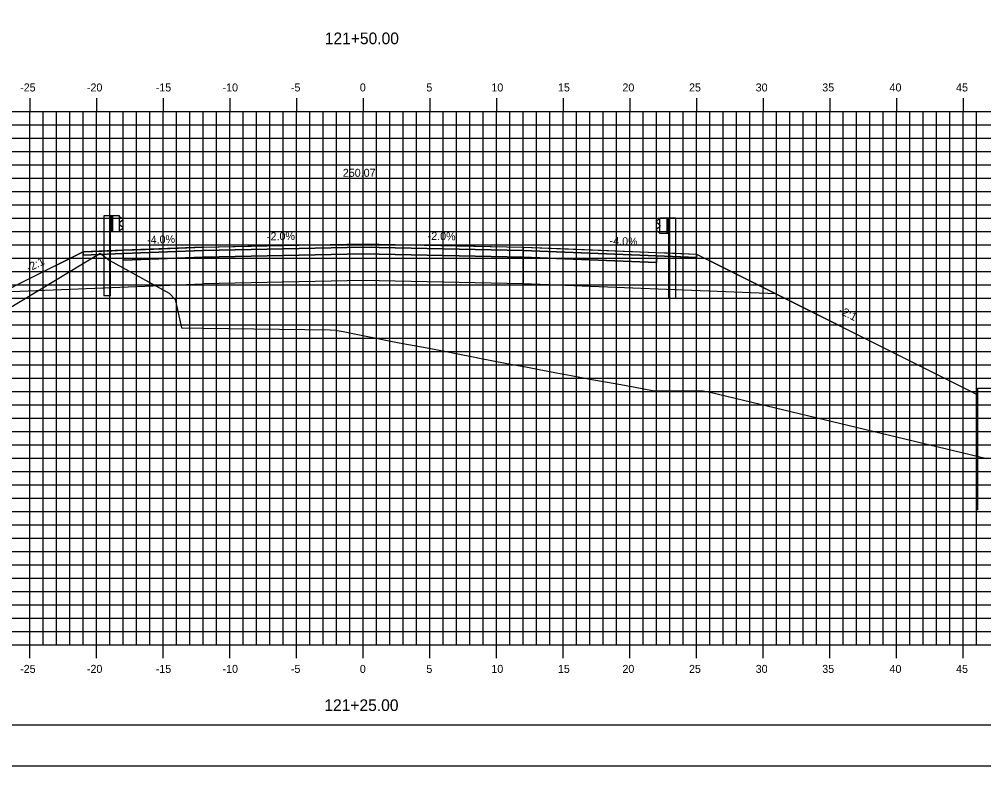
# Model space of a CAD drawing. Extents: x -22 to 1480, y -1511 to 8.
# Drawn here: x 1049.4 to 1121.7, y -1511.4 to -1455.4 of the extents above; entities that cross this region are included whole.
import ezdxf

# ---------------------------------------------------------------- set-up
doc = ezdxf.new("R2010")
doc.units = 0
for name, color, linetype in [('ANNOTATION', 7, 'Continuous'), ('BORDER', 7, 'Continuous'), ('D_Bridge_Wingwall', 7, 'Continuous'), ('D_Guardrail_Beam_Lt', 7, 'Continuous'), ('D_Guardrail_Beam_Rt', 7, 'Continuous'), ('D_Roadway_Centerline', 7, 'Continuous'), ('D_Roadway_Centerline_Text', 7, 'Continuous'), ('D_Roadway_Edge_Shoulder', 7, 'Continuous'), ('D_Roadway_Edge_TW', 7, 'Continuous'), ('D_Roadway_Pavement', 7, 'Continuous'), ('D_Roadway_SlopeLines', 7, 'Continuous'), ('D_Roadway_SubGrade', 7, 'Continuous'), ('H_V ANNOTATION', 7, 'Continuous'), ('MAJOR', 7, 'Continuous'), ('MINOR', 7, 'Continuous'), ('PLOT BOUNDARY', 7, 'Continuous'), ('S_Roadway_Centerline', 7, 'Continuous')]:
    doc.layers.add(name, color=color, linetype=linetype)

msp = doc.modelspace()

# ---------------------------------------------------------------- linework, layer by layer
at = {"layer": 'BORDER'}
msp.add_line((1000.183, -1508.331), (1160.183, -1508.331), dxfattribs=at)
at = {"layer": 'D_Bridge_Wingwall'}
msp.add_lwpolyline([(1121.282, -1492.231), (1121.282, -1483.073), (1123.425, -1483.073), (1123.425, -1483.073), (1123.425, -1492.435)], dxfattribs=at)
at = {"layer": 'D_Guardrail_Beam_Lt'}
for p, q in [((1055.753, -1470.16), (1055.753, -1476.16)), ((1056.224, -1470.16), (1055.753, -1470.16)), ((1056.912, -1470.16), (1056.224, -1470.16)), ((1056.224, -1470.16), (1056.224, -1471.327)), ((1056.287, -1470.16), (1056.287, -1471.327)), ((1056.391, -1470.16), (1056.391, -1471.327)), ((1056.912, -1471.327), (1056.912, -1470.16)), ((1056.912, -1470.243), (1056.986, -1470.258)), ((1057.002, -1470.265), (1057.145, -1470.364)), ((1056.916, -1470.708), (1056.916, -1470.778)), ((1057.145, -1470.508), (1056.95, -1470.644)), ((1056.95, -1470.843), (1057.145, -1470.979)), ((1057.145, -1471.122), (1057.002, -1471.222)), ((1056.224, -1471.327), (1056.912, -1471.327)), ((1056.245, -1476.16), (1056.245, -1471.327)), ((1056.986, -1471.229), (1056.912, -1471.243)), ((1056.245, -1476.16), (1055.753, -1476.16))]:
    msp.add_line(p, q, dxfattribs=at)
for centre, major_axis, start_param, end_param in [((1056.978, -1470.298), (0.0417, 0), 0.959931, 1.376053), ((1057.095, -1470.436), (0.0877, 0), 5.323254, 7.243116), ((1056.995, -1470.708), (-0.0789, 0), 5.323254, 6.283185), ((1056.995, -1470.778), (-0.0789, 0), 6.283185, 7.243116), ((1057.095, -1471.05), (0.0877, 0), 5.323254, 7.243116), ((1056.978, -1471.188), (0.0417, 0), 4.907132, 5.323254)]:
    msp.add_ellipse(centre, major_axis=major_axis, ratio=0.995501, start_param=start_param, end_param=end_param, dxfattribs=at)
at = {"layer": 'D_Guardrail_Beam_Rt'}
for p, q in [((1097.363, -1470.425), (1097.22, -1470.524)), ((1097.453, -1470.403), (1097.379, -1470.418)), ((1097.453, -1470.32), (1098.141, -1470.32)), ((1097.453, -1471.487), (1097.453, -1470.32)), ((1097.974, -1470.32), (1097.974, -1471.487)), ((1098.078, -1470.32), (1098.078, -1471.487)), ((1098.141, -1470.32), (1098.612, -1470.32)), ((1098.141, -1470.32), (1098.141, -1471.487)), ((1098.612, -1470.32), (1098.612, -1476.32)), ((1097.22, -1470.668), (1097.415, -1470.804)), ((1097.415, -1471.003), (1097.22, -1471.139)), ((1097.449, -1470.868), (1097.449, -1470.938)), ((1097.22, -1471.282), (1097.363, -1471.382)), ((1097.379, -1471.389), (1097.453, -1471.403)), ((1098.141, -1471.487), (1097.453, -1471.487)), ((1098.12, -1476.32), (1098.12, -1471.487)), ((1098.12, -1476.32), (1098.612, -1476.32))]:
    msp.add_line(p, q, dxfattribs=at)
for centre, major_axis, start_param, end_param in [((1097.387, -1470.458), (-0.0417, 0), 4.907132, 5.323254), ((1097.27, -1470.596), (-0.0877, 0), 5.323254, 7.243116), ((1097.27, -1471.21), (-0.0877, 0), 5.323254, 7.243116), ((1097.37, -1470.868), (0.0789, 0), 0, 0.959931), ((1097.37, -1470.938), (0.0789, 0), 5.323254, 6.283185), ((1097.387, -1471.348), (-0.0417, 0), 0.959931, 1.376053)]:
    msp.add_ellipse(centre, major_axis=major_axis, ratio=0.995501, start_param=start_param, end_param=end_param, dxfattribs=at)
at = {"layer": 'D_Roadway_Centerline'}
msp.add_lwpolyline([(1031.762, -1484.073), (1041.448, -1479.231), (1045.248, -1477.33), (1048.204, -1475.852), (1049.878, -1475.015), (1054.183, -1472.863), (1056.343, -1472.777), (1057.183, -1472.743), (1058.863, -1472.676), (1063.183, -1472.503), (1066.543, -1472.436), (1075.183, -1472.263), (1078.543, -1472.33), (1087.183, -1472.503), (1089.983, -1472.615), (1097.183, -1472.903), (1098.023, -1472.937), (1100.183, -1473.023), (1101.856, -1473.86), (1106.161, -1476.012), (1115.503, -1480.683), (1121.282, -1483.573)], dxfattribs=at)
at = {"layer": 'D_Roadway_Edge_Shoulder'}
for points in [[(1063.183, -1472.503), (1057.183, -1472.743), (1057.183, -1472.743), (1054.183, -1472.863), (1054.183, -1473.113), (1057.183, -1472.993), (1057.183, -1472.993), (1063.183, -1472.753)], [(1087.183, -1472.503), (1097.183, -1472.903), (1097.183, -1472.903), (1100.183, -1473.023), (1100.183, -1473.273), (1097.183, -1473.153), (1097.183, -1473.153), (1087.183, -1472.753)]]:
    msp.add_lwpolyline(points, close=True, dxfattribs=at)
at = {"layer": 'D_Roadway_Edge_TW'}
msp.add_lwpolyline([(1063.183, -1472.753), (1063.183, -1472.503), (1075.183, -1472.263), (1087.183, -1472.503), (1087.183, -1472.753), (1075.183, -1472.513)], close=True, dxfattribs=at)
at = {"layer": 'D_Roadway_Pavement'}
msp.add_lwpolyline([(1063.183, -1473.253), (1063.183, -1472.753), (1075.183, -1472.513), (1087.183, -1472.753), (1087.183, -1473.253), (1075.183, -1473.013)], close=True, dxfattribs=at)
for points in [[(1063.183, -1472.753), (1057.183, -1472.993), (1057.183, -1472.993), (1057.183, -1473.493), (1063.183, -1473.253), (1063.183, -1472.753)], [(1087.183, -1472.753), (1097.183, -1473.153), (1097.183, -1473.153), (1097.183, -1473.653), (1087.183, -1473.253), (1087.183, -1472.753)]]:
    msp.add_lwpolyline(points, dxfattribs=at)
at = {"layer": 'D_Roadway_SlopeLines'}
for points in [[(1054.183, -1472.863), (1031.762, -1484.073)], [(1100.183, -1473.023), (1121.282, -1483.573)]]:
    msp.add_lwpolyline(points, dxfattribs=at)
at = {"layer": 'D_Roadway_SubGrade'}
for points in [[(1063.183, -1473.253), (1057.183, -1473.493), (1057.183, -1472.993), (1054.183, -1473.113), (1054.183, -1472.863), (1048.204, -1475.852), (1063.183, -1475.253)], [(1063.183, -1475.253), (1063.183, -1473.253), (1075.183, -1473.013), (1087.183, -1473.253), (1087.183, -1475.253), (1075.183, -1475.013)], [(1087.183, -1473.253), (1097.183, -1473.653), (1097.183, -1473.153), (1100.183, -1473.273), (1100.183, -1473.023), (1106.161, -1476.012), (1087.183, -1475.253)]]:
    msp.add_lwpolyline(points, close=True, dxfattribs=at)
at = {"layer": 'MAJOR'}
for p, q in [((1050.183, -1461.329), (1050.183, -1462.331)), ((1055.183, -1461.329), (1055.183, -1462.331)), ((1060.183, -1461.329), (1060.183, -1462.331)), ((1065.183, -1461.329), (1065.183, -1462.331)), ((1070.183, -1461.329), (1070.183, -1462.331)), ((1075.183, -1461.329), (1075.183, -1462.331)), ((1080.183, -1461.329), (1080.183, -1462.331)), ((1085.183, -1461.329), (1085.183, -1462.331)), ((1090.183, -1461.329), (1090.183, -1462.331)), ((1095.183, -1461.329), (1095.183, -1462.331)), ((1100.183, -1461.329), (1100.183, -1462.331)), ((1105.183, -1461.329), (1105.183, -1462.331)), ((1110.183, -1461.329), (1110.183, -1462.331)), ((1115.183, -1461.329), (1115.183, -1462.331)), ((1120.183, -1461.329), (1120.183, -1462.331)), ((1005.183, -1462.331), (1145.183, -1462.331)), ((1005.183, -1462.331), (1145.183, -1462.331)), ((1050.183, -1502.331), (1050.183, -1462.331)), ((1055.183, -1502.331), (1055.183, -1462.331)), ((1060.183, -1502.331), (1060.183, -1462.331)), ((1065.183, -1502.331), (1065.183, -1462.331)), ((1070.183, -1502.331), (1070.183, -1462.331)), ((1075.183, -1502.331), (1075.183, -1462.331)), ((1080.183, -1502.331), (1080.183, -1462.331)), ((1085.183, -1502.331), (1085.183, -1462.331)), ((1090.183, -1502.331), (1090.183, -1462.331)), ((1095.183, -1502.331), (1095.183, -1462.331)), ((1100.183, -1502.331), (1100.183, -1462.331)), ((1105.183, -1502.331), (1105.183, -1462.331)), ((1110.183, -1502.331), (1110.183, -1462.331)), ((1115.183, -1502.331), (1115.183, -1462.331)), ((1120.183, -1502.331), (1120.183, -1462.331)), ((1005.183, -1467.331), (1145.183, -1467.331)), ((1005.183, -1472.331), (1145.183, -1472.331)), ((1005.183, -1477.331), (1145.183, -1477.331)), ((1005.183, -1482.331), (1145.183, -1482.331)), ((1005.183, -1487.331), (1145.183, -1487.331)), ((1005.183, -1492.331), (1145.183, -1492.331)), ((1005.183, -1497.331), (1145.183, -1497.331)), ((1005.183, -1502.331), (1145.183, -1502.331)), ((1005.183, -1502.331), (1145.183, -1502.331)), ((1050.183, -1503.333), (1050.183, -1502.331)), ((1055.183, -1503.333), (1055.183, -1502.331)), ((1060.183, -1503.333), (1060.183, -1502.331)), ((1065.183, -1503.333), (1065.183, -1502.331)), ((1070.183, -1503.333), (1070.183, -1502.331)), ((1075.183, -1503.333), (1075.183, -1502.331)), ((1080.183, -1503.333), (1080.183, -1502.331)), ((1085.183, -1503.333), (1085.183, -1502.331)), ((1090.183, -1503.333), (1090.183, -1502.331)), ((1095.183, -1503.333), (1095.183, -1502.331)), ((1100.183, -1503.333), (1100.183, -1502.331)), ((1105.183, -1503.333), (1105.183, -1502.331)), ((1110.183, -1503.333), (1110.183, -1502.331)), ((1115.183, -1503.333), (1115.183, -1502.331)), ((1120.183, -1503.333), (1120.183, -1502.331))]:
    msp.add_line(p, q, dxfattribs=at)
at = {"layer": 'MINOR'}
for p, q in [((1051.183, -1502.331), (1051.183, -1462.331)), ((1052.183, -1502.331), (1052.183, -1462.331)), ((1053.183, -1502.331), (1053.183, -1462.331)), ((1054.183, -1502.331), (1054.183, -1462.331)), ((1056.183, -1502.331), (1056.183, -1462.331)), ((1057.183, -1502.331), (1057.183, -1462.331)), ((1058.183, -1502.331), (1058.183, -1462.331)), ((1059.183, -1502.331), (1059.183, -1462.331)), ((1061.183, -1502.331), (1061.183, -1462.331)), ((1062.183, -1502.331), (1062.183, -1462.331)), ((1063.183, -1502.331), (1063.183, -1462.331)), ((1064.183, -1502.331), (1064.183, -1462.331)), ((1066.183, -1502.331), (1066.183, -1462.331)), ((1067.183, -1502.331), (1067.183, -1462.331)), ((1068.183, -1502.331), (1068.183, -1462.331)), ((1069.183, -1502.331), (1069.183, -1462.331)), ((1071.183, -1502.331), (1071.183, -1462.331)), ((1072.183, -1502.331), (1072.183, -1462.331)), ((1073.183, -1502.331), (1073.183, -1462.331)), ((1074.183, -1502.331), (1074.183, -1462.331)), ((1076.183, -1502.331), (1076.183, -1462.331)), ((1077.183, -1502.331), (1077.183, -1462.331)), ((1078.183, -1502.331), (1078.183, -1462.331)), ((1079.183, -1502.331), (1079.183, -1462.331)), ((1081.183, -1502.331), (1081.183, -1462.331)), ((1082.183, -1502.331), (1082.183, -1462.331)), ((1083.183, -1502.331), (1083.183, -1462.331)), ((1084.183, -1502.331), (1084.183, -1462.331)), ((1086.183, -1502.331), (1086.183, -1462.331)), ((1087.183, -1502.331), (1087.183, -1462.331)), ((1088.183, -1502.331), (1088.183, -1462.331)), ((1089.183, -1502.331), (1089.183, -1462.331)), ((1091.183, -1502.331), (1091.183, -1462.331)), ((1092.183, -1502.331), (1092.183, -1462.331)), ((1093.183, -1502.331), (1093.183, -1462.331)), ((1094.183, -1502.331), (1094.183, -1462.331)), ((1096.183, -1502.331), (1096.183, -1462.331)), ((1097.183, -1502.331), (1097.183, -1462.331)), ((1098.183, -1502.331), (1098.183, -1462.331)), ((1099.183, -1502.331), (1099.183, -1462.331)), ((1101.183, -1502.331), (1101.183, -1462.331)), ((1102.183, -1502.331), (1102.183, -1462.331)), ((1103.183, -1502.331), (1103.183, -1462.331)), ((1104.183, -1502.331), (1104.183, -1462.331)), ((1106.183, -1502.331), (1106.183, -1462.331)), ((1107.183, -1502.331), (1107.183, -1462.331)), ((1108.183, -1502.331), (1108.183, -1462.331)), ((1109.183, -1502.331), (1109.183, -1462.331)), ((1111.183, -1502.331), (1111.183, -1462.331)), ((1112.183, -1502.331), (1112.183, -1462.331)), ((1113.183, -1502.331), (1113.183, -1462.331)), ((1114.183, -1502.331), (1114.183, -1462.331)), ((1116.183, -1502.331), (1116.183, -1462.331)), ((1117.183, -1502.331), (1117.183, -1462.331)), ((1118.183, -1502.331), (1118.183, -1462.331)), ((1119.183, -1502.331), (1119.183, -1462.331)), ((1121.183, -1502.331), (1121.183, -1462.331)), ((1005.183, -1463.331), (1145.183, -1463.331)), ((1005.183, -1464.331), (1145.183, -1464.331)), ((1005.183, -1465.331), (1145.183, -1465.331)), ((1005.183, -1466.331), (1145.183, -1466.331)), ((1005.183, -1468.331), (1145.183, -1468.331)), ((1005.183, -1469.331), (1145.183, -1469.331)), ((1005.183, -1470.331), (1145.183, -1470.331)), ((1005.183, -1471.331), (1145.183, -1471.331)), ((1005.183, -1473.331), (1145.183, -1473.331)), ((1005.183, -1474.331), (1145.183, -1474.331)), ((1005.183, -1475.331), (1145.183, -1475.331)), ((1005.183, -1476.331), (1145.183, -1476.331)), ((1005.183, -1478.331), (1145.183, -1478.331)), ((1005.183, -1479.331), (1145.183, -1479.331)), ((1005.183, -1480.331), (1145.183, -1480.331)), ((1005.183, -1481.331), (1145.183, -1481.331)), ((1005.183, -1483.331), (1145.183, -1483.331)), ((1005.183, -1484.331), (1145.183, -1484.331)), ((1005.183, -1485.331), (1145.183, -1485.331)), ((1005.183, -1486.331), (1145.183, -1486.331)), ((1005.183, -1488.331), (1145.183, -1488.331)), ((1005.183, -1489.331), (1145.183, -1489.331)), ((1005.183, -1490.331), (1145.183, -1490.331)), ((1005.183, -1491.331), (1145.183, -1491.331)), ((1005.183, -1493.331), (1145.183, -1493.331)), ((1005.183, -1494.331), (1145.183, -1494.331)), ((1005.183, -1495.331), (1145.183, -1495.331)), ((1005.183, -1496.331), (1145.183, -1496.331)), ((1005.183, -1498.331), (1145.183, -1498.331)), ((1005.183, -1499.331), (1145.183, -1499.331)), ((1005.183, -1500.331), (1145.183, -1500.331)), ((1005.183, -1501.331), (1145.183, -1501.331))]:
    msp.add_line(p, q, dxfattribs=at)
at = {"layer": 'PLOT BOUNDARY'}
msp.add_lwpolyline([(992.089, -1511.39), (1162.089, -1511.39), (1162.089, -1401.39), (992.089, -1401.39)], close=True, dxfattribs=at)
at = {"layer": 'S_Roadway_Centerline'}
msp.add_lwpolyline([(1046.106, -1478.61), (1055.468, -1472.969), (1056.134, -1473.472), (1060.64, -1475.954), (1061.086, -1476.423), (1061.176, -1476.763), (1061.57, -1478.555), (1063.185, -1478.578), (1072.715, -1478.714), (1073.137, -1478.741), (1073.239, -1478.756), (1073.685, -1478.84), (1074.912, -1479.077), (1077.891, -1479.676), (1080.269, -1480.111), (1083.693, -1480.782), (1083.764, -1480.796), (1083.804, -1480.804), (1085.978, -1481.219), (1087.398, -1481.489), (1088.266, -1481.659), (1089.695, -1481.933), (1090.794, -1482.136), (1092.33, -1482.418), (1094.25, -1482.763), (1095.595, -1483.011), (1096.902, -1483.252), (1100.304, -1483.272), (1100.465, -1483.274), (1100.696, -1483.282), (1101.211, -1483.382), (1121.959, -1488.358)], dxfattribs=at)
msp.add_lwpolyline([(1046.106, -1478.61), (1055.468, -1472.969), (1056.134, -1473.472), (1060.64, -1475.954), (1061.086, -1476.423), (1061.176, -1476.763), (1061.57, -1478.555), (1063.185, -1478.578), (1072.715, -1478.714), (1073.137, -1478.741), (1073.239, -1478.756), (1073.685, -1478.84), (1074.912, -1479.077), (1077.891, -1479.676), (1080.269, -1480.111), (1083.693, -1480.782), (1083.764, -1480.796), (1083.804, -1480.804), (1085.978, -1481.219), (1087.398, -1481.489), (1088.266, -1481.659), (1089.695, -1481.933), (1090.794, -1482.136), (1092.33, -1482.418), (1094.25, -1482.763), (1095.595, -1483.011), (1096.902, -1483.252), (1100.304, -1483.272), (1100.465, -1483.274), (1100.696, -1483.282), (1101.211, -1483.382), (1121.959, -1488.358)], dxfattribs=at)

# ---------------------------------------------------------------- texts
at = {"layer": 'ANNOTATION'}
for s, rotation, p in [('-4.0%', 2.29061, (1058.999, -1472.27)), ('-2.0%', 1.14576, (1067.986, -1472.007)), ('-2.0%', 358.85424, (1080.026, -1471.96)), ('-4.0%', 357.70939, (1093.668, -1472.317)), ('-2:1', 26.56505, (1050.122, -1474.375)), ('-2:1', 333.43495, (1110.805, -1477.444))]:
    msp.add_text(s, height=0.6, rotation=rotation, dxfattribs=at).set_placement(p)
at = {"layer": 'D_Roadway_Centerline'}
for s, p in [('C', (1075.177, -1472.263)), ('L', (1075.183, -1472.271))]:
    msp.add_text(s, height=0.0146, dxfattribs=at).set_placement(p)
at = {"layer": 'D_Roadway_Centerline_Text'}
msp.add_text('250.07', height=0.6, dxfattribs=at).set_placement((1073.668, -1467.231))
at = {"layer": 'H_V ANNOTATION'}
for s, height, p in [('121+50.00', 0.875, (1072.311, -1457.288)), ('-25', 0.6, (1049.468, -1460.831)), ('-20', 0.6, (1054.476, -1460.831)), ('-15', 0.6, (1059.639, -1460.831)), ('-10', 0.6, (1064.647, -1460.831)), ('-5', 0.6, (1069.773, -1460.831)), ('0', 0.6, (1074.942, -1460.831)), ('5', 0.6, (1079.934, -1460.831)), ('10', 0.6, (1084.808, -1460.831)), ('15', 0.6, (1089.8, -1460.831)), ('20', 0.6, (1094.637, -1460.831)), ('25', 0.6, (1099.629, -1460.831)), ('30', 0.6, (1104.631, -1460.831)), ('35', 0.6, (1109.623, -1460.831)), ('40', 0.6, (1114.669, -1460.831)), ('45', 0.6, (1119.661, -1460.831)), ('-25', 0.6, (1049.468, -1504.431)), ('-20', 0.6, (1054.476, -1504.431)), ('-15', 0.6, (1059.639, -1504.431)), ('-10', 0.6, (1064.647, -1504.431)), ('-5', 0.6, (1069.773, -1504.431)), ('0', 0.6, (1074.942, -1504.431)), ('5', 0.6, (1079.934, -1504.431)), ('10', 0.6, (1084.808, -1504.431)), ('15', 0.6, (1089.8, -1504.431)), ('20', 0.6, (1094.637, -1504.431)), ('25', 0.6, (1099.629, -1504.431)), ('30', 0.6, (1104.631, -1504.431)), ('35', 0.6, (1109.623, -1504.431)), ('40', 0.6, (1114.669, -1504.431)), ('45', 0.6, (1119.661, -1504.431)), ('121+25.00', 0.875, (1072.28, -1507.288))]:
    msp.add_text(s, height=height, dxfattribs=at).set_placement(p)

doc.saveas('drawing.dxf')
